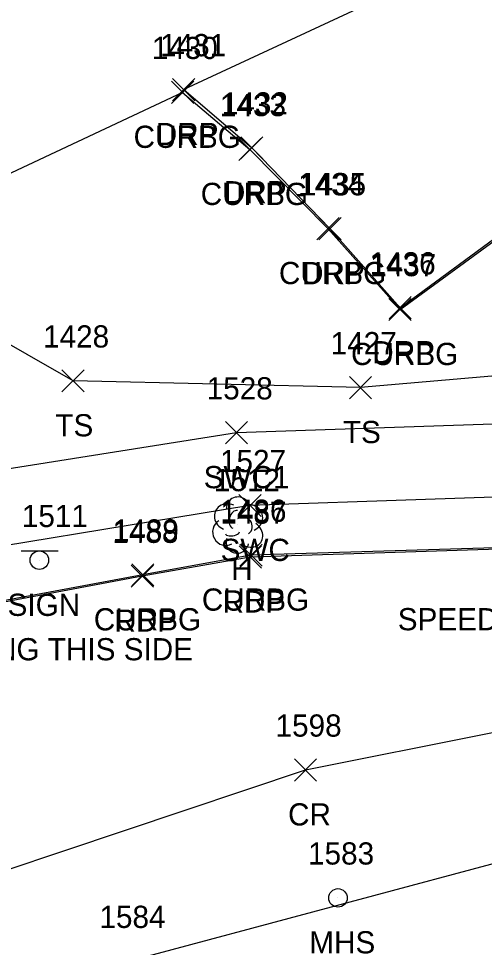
# Model space of a CAD drawing. Extents: x 1715662 to 1717487, y 887396 to 890004.
# Drawn here: x 1716174.2 to 1716216.1, y 888223.5 to 888307.2 of the extents above; entities that cross this region are included whole.
import ezdxf

# ---------------------------------------------------------------- set-up
doc = ezdxf.new("R2010")
doc.units = 0
for name, color, linetype in [('L_A', 7, 'Continuous'), ('L_I', 7, 'Continuous'), ('L_TIC', 7, 'Continuous'), ('LELB', 7, 'Continuous'), ('LSOGP', 7, 'Continuous'), ('LTD', 7, 'Continuous'), ('P_A', 7, 'Continuous'), ('P_I', 7, 'Continuous'), ('P_TIC', 7, 'Continuous'), ('PET', 7, 'Continuous'), ('PRC', 7, 'Continuous'), ('R_A', 7, 'Continuous'), ('R_I', 7, 'Continuous'), ('R_TIC', 7, 'Continuous'), ('RC', 7, 'Continuous'), ('RDP', 7, 'Continuous'), ('RSW', 7, 'Continuous'), ('S_A', 7, 'Continuous'), ('S_C', 7, 'Continuous'), ('S_I', 7, 'Continuous'), ('SSGN', 7, 'Continuous'), ('U_A', 7, 'Continuous'), ('U_I', 7, 'Continuous'), ('USMH', 7, 'Continuous')]:
    doc.layers.add(name, color=color, linetype=linetype)

msp = doc.modelspace()

# ---------------------------------------------------------------- linework, layer by layer
at = {"layer": 'L_TIC'}
for points in [[(1716178.055, 888273.559), (1716180.055, 888275.559)], [(1716180.055, 888273.559), (1716178.055, 888275.559)], [(1716203.949, 888272.952), (1716205.949, 888274.952)], [(1716205.949, 888272.952), (1716203.949, 888274.952)]]:
    msp.add_lwpolyline(points, dxfattribs=at)
at = {"layer": 'LELB'}
msp.add_lwpolyline([(1716253.109, 888276.938), (1716230.334, 888276.139), (1716204.949, 888273.952), (1716179.055, 888274.559), (1716158.545, 888286.283)], dxfattribs=at)
at = {"layer": 'LSOGP'}
msp.add_lwpolyline([(1716309.755, 888326.671), (1716279.78, 888323.124), (1716274.118, 888322.974), (1716268.456, 888322.825), (1716262.794, 888322.675), (1716257.132, 888322.526), (1716251.47, 888322.376), (1716245.807, 888322.227), (1716240.145, 888322.077), (1716234.483, 888321.927), (1716189.024, 888300.781), (1716188.924, 888300.532), (1716158.544, 888286.279), (1716143.729, 888281.039), (1716136.652, 888281.122), (1716129.548, 888281.147), (1716125.193, 888279.219), (1716121.765, 888276.546), (1716112.533, 888269.132), (1716099.332, 888263.72), (1716089.76, 888259.757), (1716076.635, 888254.355), (1716079.329, 888227.083), (1716083.381, 888221.281)], dxfattribs=at)
at = {"layer": 'LTD'}
msp.add_line((1716193.868, 888261.623), (1716193.868, 888261.623), dxfattribs=at)
msp.add_line((1716193.868, 888261.623), (1716193.868, 888261.623), dxfattribs=at)
msp.add_arc((1716193.915, 888263.057), 1.047, 335.52715, 180.95627, dxfattribs=at)
for centre, major_axis, ratio, start_param, end_param in [((1716193.076, 888262.289), (1.21, -0.512), 0.895232, 1.570796, 4.712389), ((1716194.909, 888262.206), (-1.141, -0.483), 0.949671, 1.570796, 4.712389), ((1716193.659, 888262.081), (-0.208, -0.792), 0.645439, 3.141593, 6.283185), ((1716194.368, 888261.456), (-0.5, 0.667), 0.989748, 3.141593, 6.283185), ((1716192.785, 888260.914), (0.584, -1.042), 0.959034, 3.141593, 6.283185), ((1716194.868, 888260.79), (-1.09, 0.792), 0.841452, 1.570796, 4.712389), ((1716193.41, 888260.873), (-0.625, -0.083), 0.423636, 0, 3.141593), ((1716193.868, 888260.123), (0.265, 1.061), 0.942809, 1.570796, 4.712389)]:
    msp.add_ellipse(centre, major_axis=major_axis, ratio=ratio, start_param=start_param, end_param=end_param, dxfattribs=at)
at = {"layer": 'P_TIC'}
for points in [[(1716194.021, 888257.693), (1716196.021, 888259.693)], [(1716196.021, 888257.693), (1716194.021, 888259.693)], [(1716184.292, 888255.969), (1716186.292, 888257.969)], [(1716186.292, 888255.969), (1716184.292, 888257.969)], [(1716198.989, 888238.524), (1716200.989, 888240.524)], [(1716200.989, 888238.524), (1716198.989, 888240.524)]]:
    msp.add_lwpolyline(points, dxfattribs=at)
at = {"layer": 'PET'}
msp.add_lwpolyline([(1716291.61, 888264.06), (1716269.77, 888261.49), (1716262.966, 888260.72), (1716255.802, 888260.488), (1716249.474, 888260.34), (1716222.977, 888259.577), (1716195.021, 888258.693), (1716185.292, 888256.969), (1716167.728, 888253.671), (1716163.419, 888252.514), (1716159.416, 888251.015), (1716151.29, 888247.477), (1716119.218, 888232.856), (1716096.012, 888221.572), (1716087.754, 888207.546)], dxfattribs=at)
at = {"layer": 'PRC'}
for points in [[(1716612.851, 888359.685), (1716612.17, 888345.494), (1716610.226, 888325.048), (1716599.913, 888295.769), (1716584.781, 888274.259), (1716560.313, 888253.421), (1716535.276, 888241.323), (1716471.977, 888238.418), (1716446.909, 888240.452), (1716423.435, 888242.235), (1716395.991, 888243.462), (1716360.07, 888243.385), (1716329.012, 888242.881), (1716285.787, 888240.518), (1716253.168, 888237.299), (1716220.467, 888232.037), (1716184.129, 888222.299), (1716155.748, 888211.826), (1716125.795, 888199.816), (1716096.662, 888186.569)], [(1716091.287, 888196.834), (1716134.452, 888216.07), (1716167.358, 888228.61), (1716199.989, 888239.524), (1716233.063, 888246.142), (1716254.664, 888248.77)]]:
    msp.add_lwpolyline(points, dxfattribs=at)
at = {"layer": 'R_TIC'}
for points in [[(1716188.024, 888299.786), (1716190.024, 888301.786)], [(1716190.024, 888299.786), (1716188.024, 888301.786)], [(1716187.928, 888299.535), (1716189.928, 888301.535)], [(1716189.928, 888299.535), (1716187.928, 888301.535)], [(1716194.154, 888294.541), (1716196.154, 888296.541)], [(1716196.154, 888294.541), (1716194.154, 888296.541)], [(1716193.975, 888294.39), (1716195.975, 888296.39)], [(1716195.975, 888294.39), (1716193.975, 888296.39)], [(1716201.018, 888287.267), (1716203.018, 888289.267)], [(1716203.018, 888287.267), (1716201.018, 888289.267)], [(1716201.194, 888287.263), (1716203.194, 888289.263)], [(1716203.194, 888287.263), (1716201.194, 888289.263)], [(1716207.506, 888279.981), (1716209.506, 888281.981)], [(1716209.506, 888279.981), (1716207.506, 888281.981)], [(1716207.512, 888280.139), (1716209.512, 888282.139)], [(1716209.512, 888280.139), (1716207.512, 888282.139)], [(1716192.784, 888268.889), (1716194.784, 888270.889)], [(1716194.784, 888268.889), (1716192.784, 888270.889)], [(1716193.985, 888262.34), (1716195.985, 888264.34)], [(1716195.985, 888262.34), (1716193.985, 888264.34)], [(1716194.076, 888257.866), (1716196.076, 888259.866)], [(1716196.076, 888257.866), (1716194.076, 888259.866)], [(1716184.345, 888256.088), (1716186.345, 888258.088)], [(1716186.345, 888256.088), (1716184.345, 888258.088)]]:
    msp.add_lwpolyline(points, dxfattribs=at)
at = {"layer": 'RC'}
for points in [[(1716188.928, 888300.535), (1716194.975, 888295.39), (1716202.018, 888288.267), (1716208.506, 888280.981), (1716229.357, 888296.208), (1716232.854, 888297.772), (1716235.937, 888298.37), (1716261.527, 888298.996), (1716287.483, 888299.431)], [(1716291.602, 888264.18), (1716269.776, 888261.634), (1716262.937, 888260.816), (1716255.801, 888260.598), (1716249.466, 888260.49), (1716223.046, 888259.698), (1716195.076, 888258.866), (1716185.345, 888257.088), (1716167.749, 888253.823), (1716163.381, 888252.587), (1716159.315, 888251.172), (1716151.289, 888247.636), (1716119.139, 888233.028), (1716095.815, 888221.68), (1716087.942, 888207.956)]]:
    msp.add_lwpolyline(points, dxfattribs=at)
at = {"layer": 'RDP'}
msp.add_lwpolyline([(1716189.024, 888300.786), (1716195.154, 888295.541), (1716202.194, 888288.263), (1716208.512, 888281.139), (1716229.206, 888296.357), (1716232.872, 888297.892), (1716235.84, 888298.504), (1716261.496, 888299.043), (1716287.478, 888299.606), (1716290.586, 888299.167), (1716294.21, 888298.032), (1716297.419, 888296.376), (1716300.338, 888294.175), (1716302.933, 888291.519), (1716305.656, 888287.714), (1716307.48, 888284.067), (1716308.904, 888279.993), (1716309.436, 888276.784), (1716309.376, 888273.785), (1716308.107, 888269.878), (1716306.525, 888267.198), (1716305.127, 888265.54)], dxfattribs=at)
at = {"layer": 'RSW'}
for points in [[(1716308.53, 888273.184), (1716291.3, 888272.553), (1716259.154, 888271.89), (1716226.643, 888270.982), (1716193.784, 888269.889), (1716164.394, 888265.223), (1716160.716, 888264.617), (1716155.847, 888262.476), (1716141.722, 888256.045), (1716137.135, 888254.024), (1716108.704, 888240.881), (1716099.258, 888236.591), (1716079.333, 888227.087)], [(1716304.924, 888266.392), (1716291.325, 888266.062), (1716259.803, 888265.285), (1716226.621, 888264.409), (1716194.985, 888263.34), (1716161.734, 888257.864), (1716139.704, 888247.707), (1716119.85, 888238.533), (1716083.389, 888221.288)]]:
    msp.add_lwpolyline(points, dxfattribs=at)
at = {"layer": 'SSGN'}
for p, q in [((1716174.379, 888259.249), (1716177.712, 888259.249)), ((1716176.025, 888258.415), (1716176.025, 888258.415))]:
    msp.add_line(p, q, dxfattribs=at)
msp.add_circle((1716176.025, 888258.415), 0.833, dxfattribs=at)
at = {"layer": 'USMH'}
for p, q in [((1716202.914, 888228.007), (1716202.914, 888228.007)), ((1716203.748, 888228.007), (1716203.748, 888228.007))]:
    msp.add_line(p, q, dxfattribs=at)
msp.add_circle((1716202.914, 888228.007), 0.833, dxfattribs=at)

# ---------------------------------------------------------------- texts
at = {"layer": 'L_A'}
for s, p in [('TS', (1716177.464, 888269.559)), ('TS', (1716203.358, 888268.952)), ('H', (1716193.301, 888256.623))]:
    msp.add_text(s, height=2, dxfattribs=at).set_placement(p)
at = {"layer": 'L_I'}
for s, p in [('1428', (1716176.362, 888277.559)), ('1427', (1716202.256, 888276.952)), ('1512', (1716191.742, 888264.623))]:
    msp.add_text(s, height=2, dxfattribs=at).set_placement(p)
at = {"layer": 'P_A'}
for s, p in [('RDP', (1716192.509, 888253.693)), ('RDP', (1716182.78, 888251.969)), ('CR', (1716198.422, 888234.524))]:
    msp.add_text(s, height=2, dxfattribs=at).set_placement(p)
at = {"layer": 'P_I'}
for s, p in [('1487', (1716192.328, 888261.693)), ('1488', (1716182.599, 888259.969)), ('1598', (1716197.296, 888242.524)), ('1584', (1716181.436, 888225.299))]:
    msp.add_text(s, height=2, dxfattribs=at).set_placement(p)
at = {"layer": 'R_A'}
for s, p in [('CURBG', (1716184.511, 888295.535)), ('DRP', (1716186.512, 888295.786)), ('CURBG', (1716190.558, 888290.39)), ('DRP', (1716192.642, 888290.541)), ('CURBG', (1716197.601, 888283.267)), ('DRP', (1716199.682, 888283.263)), ('DRP', (1716206, 888276.139)), ('CURBG', (1716204.089, 888275.981)), ('SWC1', (1716190.823, 888264.889)), ('SWC', (1716192.347, 888258.34)), ('CURBG', (1716190.659, 888253.866)), ('CURBG', (1716180.928, 888252.088))]:
    msp.add_text(s, height=2, dxfattribs=at).set_placement(p)
at = {"layer": 'R_I'}
for s, p in [('1431', (1716186.898, 888303.786)), ('1430', (1716186.149, 888303.535)), ('1433', (1716192.282, 888298.39)), ('1432', (1716192.461, 888298.541)), ('1434', (1716199.325, 888291.267)), ('1435', (1716199.501, 888291.263)), ('1436', (1716205.764, 888284.139)), ('1437', (1716205.813, 888283.981)), ('1528', (1716191.091, 888272.889)), ('1527', (1716192.292, 888266.34)), ('1486', (1716192.328, 888261.866)), ('1489', (1716182.644, 888260.088))]:
    msp.add_text(s, height=2, dxfattribs=at).set_placement(p)
at = {"layer": 'S_A'}
msp.add_text('SIGN', height=2, dxfattribs=at).set_placement((1716173.163, 888253.395))
at = {"layer": 'S_C'}
for s, p in [('SPEED LIMIT 25', (1716208.3, 888252.099)), ('NO PARKING THIS SIDE', (1716159.25, 888249.395))]:
    msp.add_text(s, height=2, dxfattribs=at).set_placement(p)
at = {"layer": 'S_I'}
msp.add_text('1511', height=2, dxfattribs=at).set_placement((1716174.447, 888261.395))
at = {"layer": 'U_A'}
msp.add_text('MHS', height=2, dxfattribs=at).set_placement((1716200.332, 888223.007))
at = {"layer": 'U_I'}
msp.add_text('1583', height=2, dxfattribs=at).set_placement((1716200.222, 888231.007))

doc.saveas('drawing.dxf')
